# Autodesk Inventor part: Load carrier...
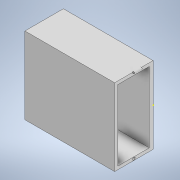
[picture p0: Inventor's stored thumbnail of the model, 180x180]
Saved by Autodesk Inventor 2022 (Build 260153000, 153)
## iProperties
Created: 2021-07
Part Number: Load carrier...
Material: Generic
Document SubType Name: Modeling
Designer: Astami
Density: 1 g/cm^3
Appearance: Default
Author: Astami
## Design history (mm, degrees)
sketch "Sketch1"
  geometry: L1 (-350, -300)-(350, -300); L2 (350, -300)-(350, 300); L3 (350, 300)-(-350, 300); L4 (-350, 300)-(-350, -300); L5 (-350, -300)-(350, 300); L6 (350, -300)-(-350, 300); 1 further point
  constraints: 12 end point, 2 midpoint, 2 parallel, 1 horizontal, 1 perpendicular
  dimensions: "d0" = 700 distance of L3.end L2.end; "d1" = 600 distance of L2.end L1.end
extrude "Extrusion1" new body sketch "Sketch1" distance "d2" = 300; taper "d3" = 0 deg
sketch "Sketch4"
  geometry: L1 (-50, 550)-(-250, 550); L2 (-250, 550)-(-250, 50); L3 (-250, 50)-(-50, 50); L4 (-50, 50)-(-50, 550); L5 (0, 0)-(-300, 0) reference; L6 (0, 0)-(0, 600) reference; L7 (0, 600)-(-300, 600) reference; L8 (-300, 0)-(-300, 600) reference; 1 further point
  constraints: 8 end point, 2 parallel, 1 horizontal, 1 perpendicular
  dimensions: "d11" = 50 distance between parallel lines of L5 L3; "d12" = 50 distance between parallel lines of L6 L4; "d13" = 50 distance between parallel lines of L7 L1; "d14" = 50 distance between parallel lines of L8 L2
extrude "Extrusion4" cut sketch "Sketch4" distance "d15" = 650; taper "d16" = 0 deg
sketch "Sketch5"
  geometry: 1 further point
sketch "Sketch6"
  geometry: L1 (0, 600)-(-300, 600) reference; L2 (-621.16, 600)-(-561.16, 600); L3 (-561.16, 600)-(-561.16, 595); L4 (-561.16, 595)-(-621.16, 595); L5 (-621.16, 595)-(-621.16, 600); 2 further points
  constraints: 8 end point, 2 parallel, 1 horizontal, 1 perpendicular, 1 point on line
  dimensions: "d17" = 60 distance of L3.end L4.end; "d18" = 5 distance of L2.end L3.end
extrude "Extrusion5" join sketch "Sketch6" distance "d19" = 1; taper "d20" = 0 deg
sketch "Sketch7"
  geometry: 1 further point
sketch "Sketch11"
  geometry: L1 (0, 600)-(-300, 600) reference; L2 (-159.852, 600)-(-99.852, 600); L3 (-99.852, 600)-(-99.852, 595); L4 (-99.852, 595)-(-159.852, 595); L5 (-159.852, 595)-(-159.852, 600); 3 further points
  constraints: 8 end point, 2 parallel, 1 horizontal, 1 perpendicular
  dimensions: "d31" = 60 distance of L3.end L4.end; "d32" = 5 distance of L2.end L3.end
extrude "Extrusion9" join sketch "Sketch11" distance "d33" = 1; taper "d34" = 0 deg
sketch "Sketch12"
  geometry: C1 r 7.5 at (7.902, 7.336); C2 r 5 at (7.902, 7.336); 1 further point
  constraints: 2 centre point, 1 coincident
  dimensions: "d35" = 15 diameter of C1; "d36" = 10 diameter of C2
sketch "Sketch13"
  geometry: 1 further point
sketch "Sketch14"
  geometry: C1 r 7.5 at (-7.956, 7.288); C2 r 5 at (-7.956, 7.288); 1 further point
  constraints: 2 centre point, 1 coincident
  dimensions: "d37" = 15 diameter of C1; "d38" = 10 diameter of C2
extrude "Extrusion10" join sketch "Sketch14" distance "d39" = 60; taper "d40" = 0 deg
extrude "Extrusion11" join sketch "Sketch12" distance "d41" = 60; taper "d42" = 0 deg
sketch "Sketch15"
  geometry: C1 r 5 at (-7.902, 7.336); A1 r 7.5 centre (-7.902, 7.336) between (-0.775, 5) and (-1, 4.402) reference; 1 further point
  constraints: 1 centre point, 1 coincident
  dimensions: "d43" = 10 diameter of C1
extrude "Extrusion12" cut sketch "Sketch15" distance "d44" = 60; taper "d45" = 0 deg
sketch "Sketch16"
  geometry: C1 r 5 at (-7.902, 7.336); A1 r 7.5 centre (-7.902, 7.336) between (-0.775, 5) and (-1, 4.402) reference; 1 further point
  constraints: 1 centre point, 1 coincident
  dimensions: "d46" = 10 diameter of C1
extrude "Extrusion13" cut sketch "Sketch16" distance "d47" = 60; taper "d48" = 0 deg
sketch "Sketch17"
  geometry: 1 further point
sketch "Sketch22"
  geometry: L1 (-350, 300)-(350, 300) reference; L2 (350, 300)-(350, -300) reference; L3 (-350, 250)-(300, 250) reference; L4 (-350, -300)-(-350, 300) reference; L5 (350, -300)-(-350, -300) reference; L6 (-350, -250)-(300, -250) reference; C1 r 25 at (150, 250); C2 r 25 at (-150, 250); C3 r 25 at (150, -250); C4 r 25 at (-150, -250); 1 further point
  constraints: 4 centre point, 2 point on line
  dimensions: "d66" = 50 diameter of C1; "d67" = 50 distance from line of C1.centre L1; "d68" = 200 distance from line of L2 C1.centre; "d69" = 50 diameter of C2; "d70" = 200 distance from line of C2.centre L4; "d71" = 50 diameter of C3; "d72" = 50 distance from line of C3.centre L5; "d73" = 200 distance from line of L2 C3.centre; "d74" = 50 diameter of C4; "d75" = 50 distance from line of C4.centre L5 (derived); "d76" = 200 distance from line of C4.centre L4
extrude "Extrusion17" cut sketch "Sketch22" distance "d77" = 25; taper "d78" = 0 deg
sketch "Sketch23"
  geometry: L1 (-30, 575.216)-(-275, 575.216); L2 (-275, 575.216)-(-275, 25); L3 (-275, 25)-(-30, 25); L4 (-30, 25)-(-30, 575.216); L5 (0, 0)-(0, 600) reference; L6 (0, 0)-(-300, 0) reference; L7 (-300, 0)-(-300, 600) reference; L8 (-159.852, 600)-(-300, 600) reference; 1 further point
  constraints: 8 end point, 2 parallel, 1 horizontal, 1 perpendicular
  dimensions: "d79" = 30 distance between parallel lines of L4 L5; "d80" = 25 distance between parallel lines of L6 L3; "d81" = 25 distance between parallel lines of L2 L7; "d82" = 24.7836 distance between parallel lines of L1 L8
extrude "Extrusion18" cut sketch "Sketch23" distance "d83" = 675; taper "d84" = 0 deg
sketch "Sketch24"
  geometry: L1 (0, 0)-(0, 600) reference; L2 (-300, 0)-(-300, 600) reference; L3 (0, 0)-(-300, 0) reference; C1 r 10 at (-150, 12.5); 1 further point
  constraints: 1 centre point
  dimensions: "d85" = 20 diameter of C1; "d86" = 150 distance from line of L1 C1.centre; "d87" = 150 distance from line of C1.centre L2 (derived); "d88" = 12.5 distance from line of L3 C1.centre
extrude "Extrusion19" cut sketch "Sketch24" distance "d89" = 50; taper "d90" = 0 deg
body "Solid1"
